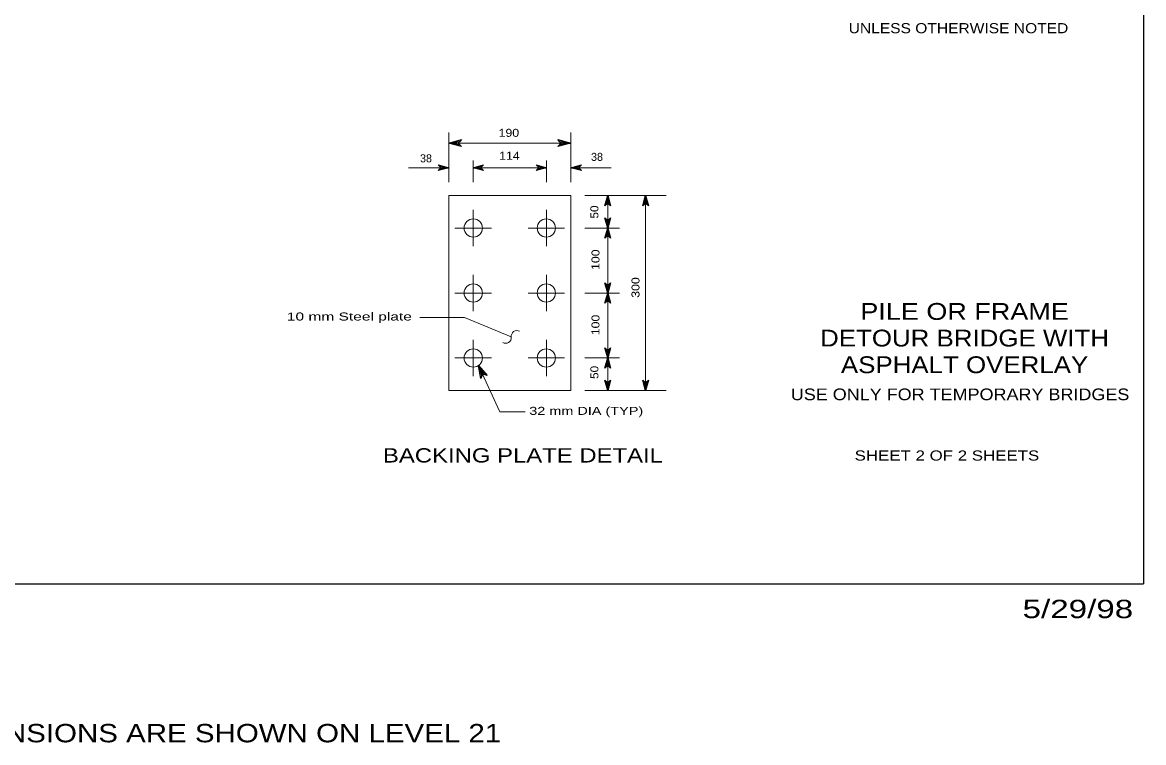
# Model space of a CAD drawing. Extents: x 13426 to 15509, y -9298 to -5111.
# Drawn here: x 15326 to 15509.2, y -5349.3 to -5231.6 of the extents above; entities that cross this region are included whole.
import ezdxf
from ezdxf.enums import TextEntityAlignment as Align

# ---------------------------------------------------------------- set-up
doc = ezdxf.new("R2010")
doc.units = 0
doc.header["$LTSCALE"] = 0.52
for name, color, linetype, lineweight in [('1', 7, 'Continuous', 13), ('15', 7, 'Continuous', 13), ('16', 7, 'Continuous', 25), ('20', 7, 'Continuous', 13), ('3', 7, 'Continuous', 25), ('30', 7, 'Continuous', 25)]:
    doc.layers.add(name, color=color, linetype=linetype, lineweight=lineweight)
doc.layers.add('19', color=7, linetype='Continuous')
doc.layers.add('32', color=7, linetype='Continuous')

msp = doc.modelspace()

# ---------------------------------------------------------------- linework, layer by layer
at = {"layer": '1'}
for p, q in [((15395.687, -5259.907), (15415.586, -5259.907)), ((15415.586, -5259.907), (15415.586, -5291.746))]:
    msp.add_line(p, q, dxfattribs=at)
msp.add_lwpolyline([(15395.687, -5259.907), (15395.687, -5291.746), (15415.586, -5291.746)], dxfattribs=at)
at = {"layer": '15'}
for p, q in [((15395.687, -5257.745), (15395.687, -5249.617)), ((15415.586, -5257.745), (15415.586, -5249.617)), ((15395.687, -5251.346), (15415.586, -5251.346)), ((15389.109, -5255.359), (15395.687, -5255.359)), ((15399.667, -5257.745), (15399.667, -5254.166)), ((15399.667, -5255.359), (15411.606, -5255.359)), ((15411.606, -5257.745), (15411.606, -5254.166)), ((15415.586, -5255.359), (15422.164, -5255.359)), ((15417.863, -5259.907), (15431.195, -5259.907)), ((15427.811, -5259.907), (15427.811, -5291.746)), ((15399.667, -5265.214), (15399.667, -5262.229)), ((15411.606, -5265.214), (15411.606, -5262.229)), ((15399.667, -5265.214), (15396.682, -5265.214)), ((15399.667, -5265.214), (15402.651, -5265.214)), ((15399.667, -5265.214), (15399.667, -5268.199)), ((15411.606, -5265.214), (15408.621, -5265.214)), ((15411.606, -5265.214), (15414.591, -5265.214)), ((15411.606, -5265.214), (15411.606, -5268.199)), ((15417.863, -5265.214), (15423.57, -5265.214)), ((15399.667, -5275.826), (15399.667, -5272.842)), ((15411.606, -5275.826), (15411.606, -5272.842)), ((15399.667, -5275.826), (15396.682, -5275.826)), ((15399.667, -5275.826), (15402.651, -5275.826)), ((15399.667, -5275.826), (15399.667, -5278.812)), ((15411.606, -5275.826), (15408.621, -5275.826)), ((15411.606, -5275.826), (15414.591, -5275.826)), ((15411.606, -5275.826), (15411.606, -5278.812)), ((15417.863, -5275.826), (15423.57, -5275.826)), ((15398.214, -5279.815), (15405.862, -5282.963)), ((15399.667, -5286.439), (15399.667, -5283.455)), ((15411.606, -5286.439), (15411.606, -5283.455)), ((15399.667, -5286.439), (15396.682, -5286.439)), ((15399.667, -5286.439), (15402.651, -5286.439)), ((15399.667, -5286.439), (15399.667, -5289.424)), ((15411.606, -5286.439), (15408.621, -5286.439)), ((15411.606, -5286.439), (15414.591, -5286.439)), ((15411.606, -5286.439), (15411.606, -5289.424)), ((15417.863, -5286.439), (15423.57, -5286.439)), ((15417.863, -5291.746), (15431.195, -5291.746))]:
    msp.add_line(p, q, dxfattribs=at)
for points in [[(15421.633, -5259.907), (15421.633, -5265.214), (15421.633, -5275.826), (15421.633, -5286.439), (15421.633, -5291.746)], [(15400.535, -5287.653), (15404.025, -5295.222), (15408.122, -5295.222)]]:
    msp.add_lwpolyline(points, dxfattribs=at)
for centre, start, end in [((15404.9427, -5283.109), 239.84377, 5.31451), ((15406.7915, -5282.8989), 62.1777, 187.64844)]:
    msp.add_arc(centre, 0.9305, start, end, dxfattribs=at)
at = {"layer": '16'}
for points in [[(15397.444, -5251.576), (15397.769, -5251.914), (15395.687, -5251.346), (15397.769, -5250.778), (15397.444, -5251.116), (15395.687, -5251.346), (15397.444, -5251.576), (15397.214, -5251.346), (15397.444, -5251.116)], [(15413.828, -5251.116), (15413.504, -5250.778), (15415.586, -5251.346), (15413.504, -5251.914), (15413.828, -5251.576), (15415.586, -5251.346), (15413.828, -5251.116), (15414.058, -5251.346), (15413.828, -5251.576)], [(15394.222, -5255.167), (15393.952, -5254.886), (15395.687, -5255.359), (15393.952, -5255.832), (15394.222, -5255.551), (15395.687, -5255.359), (15394.222, -5255.167), (15394.414, -5255.359), (15394.222, -5255.551)], [(15401.073, -5255.543), (15401.333, -5255.813), (15399.667, -5255.359), (15401.333, -5254.905), (15401.073, -5255.175), (15399.667, -5255.359), (15401.073, -5255.543), (15400.889, -5255.359), (15401.073, -5255.175)], [(15410.2, -5255.175), (15409.941, -5254.905), (15411.606, -5255.359), (15409.941, -5255.813), (15410.2, -5255.543), (15411.606, -5255.359), (15410.2, -5255.175), (15410.384, -5255.359), (15410.2, -5255.543)], [(15417.051, -5255.551), (15417.321, -5255.832), (15415.586, -5255.359), (15417.321, -5254.886), (15417.051, -5255.167), (15415.586, -5255.359), (15417.051, -5255.551), (15416.859, -5255.359), (15417.051, -5255.167)], [(15421.449, -5261.313), (15421.178, -5261.573), (15421.633, -5259.907), (15422.087, -5261.573), (15421.817, -5261.313), (15421.633, -5259.907), (15421.449, -5261.313), (15421.633, -5261.129), (15421.817, -5261.313)], [(15427.627, -5261.313), (15427.357, -5261.573), (15427.811, -5259.907), (15428.266, -5261.573), (15427.995, -5261.313), (15427.811, -5259.907), (15427.627, -5261.313), (15427.811, -5261.129), (15427.995, -5261.313)], [(15421.817, -5263.808), (15422.087, -5263.548), (15421.633, -5265.214), (15421.178, -5263.548), (15421.449, -5263.808), (15421.633, -5265.214), (15421.817, -5263.808), (15421.633, -5263.992), (15421.449, -5263.808)], [(15421.449, -5266.62), (15421.178, -5266.879), (15421.633, -5265.214), (15422.087, -5266.879), (15421.817, -5266.62), (15421.633, -5265.214), (15421.449, -5266.62), (15421.633, -5266.436), (15421.817, -5266.62)], [(15421.817, -5274.42), (15422.087, -5274.161), (15421.633, -5275.826), (15421.178, -5274.161), (15421.449, -5274.42), (15421.633, -5275.826), (15421.817, -5274.42), (15421.633, -5274.605), (15421.449, -5274.42)], [(15421.449, -5277.233), (15421.178, -5277.492), (15421.633, -5275.826), (15422.087, -5277.492), (15421.817, -5277.233), (15421.633, -5275.826), (15421.449, -5277.233), (15421.633, -5277.049), (15421.817, -5277.233)], [(15421.817, -5285.033), (15422.087, -5284.774), (15421.633, -5286.439), (15421.178, -5284.774), (15421.449, -5285.033), (15421.633, -5286.439), (15421.817, -5285.033), (15421.633, -5285.217), (15421.449, -5285.033)], [(15421.449, -5287.845), (15421.178, -5288.105), (15421.633, -5286.439), (15422.087, -5288.105), (15421.817, -5287.845), (15421.633, -5286.439), (15421.449, -5287.845), (15421.633, -5287.662), (15421.817, -5287.845)], [(15401.063, -5289.345), (15400.891, -5289.781), (15400.535, -5287.653), (15401.923, -5289.306), (15401.48, -5289.153), (15400.535, -5287.653), (15401.063, -5289.345), (15401.175, -5289.04), (15401.48, -5289.153)], [(15421.817, -5290.34), (15422.087, -5290.08), (15421.633, -5291.746), (15421.178, -5290.08), (15421.449, -5290.34), (15421.633, -5291.746), (15421.817, -5290.34), (15421.633, -5290.524), (15421.449, -5290.34)], [(15427.995, -5290.34), (15428.266, -5290.08), (15427.811, -5291.746), (15427.357, -5290.08), (15427.627, -5290.34), (15427.811, -5291.746), (15427.995, -5290.34), (15427.811, -5290.524), (15427.627, -5290.34)]]:
    msp.add_lwpolyline(points, dxfattribs=at)
at = {"layer": '20'}
msp.add_line((15390.956, -5279.815), (15398.214, -5279.815), dxfattribs=at)
at = {"layer": '3', "lineweight": 13}
for centre in [(15399.6665, -5265.2136), (15411.6059, -5265.2136), (15399.6665, -5275.8264), (15411.6059, -5275.8264), (15399.6665, -5286.4392), (15411.6059, -5286.4392)]:
    msp.add_circle(centre, 1.4924, dxfattribs=at)
at = {"layer": '30'}
for p in [(15509.151, -5111.081), (15181.119, -5323.3)]:
    msp.add_line(p, (15509.151, -5323.3), dxfattribs=at)

# ---------------------------------------------------------------- texts
at = {"layer": '1', "width": 1.35}
msp.add_text('5/29/98', height=3, dxfattribs=at).set_placement((15498.4185, -5328.93), align=Align.CENTER)
at = {"layer": '1', "width": 1.2}
msp.add_text('ENGLISH DIMENSIONS ARE SHOWN ON LEVEL 21', height=3, dxfattribs=at).set_placement((15288.661, -5349.212))
at = {"layer": '19', "width": 1.15}
for s, height, p in [('UNLESS OTHERWISE NOTED', 1.653, (15478.9175, -5233.398)), ('190', 1.307, (15405.4815, -5250.316)), ('114', 1.307, (15405.5705, -5254.055))]:
    msp.add_text(s, height=height, dxfattribs=at).set_placement(p, align=Align.CENTER)
at = {"layer": '19'}
for p in [(15391.9465, -5254.484), (15419.8765, -5254.242)]:
    msp.add_text('38', height=1.307, dxfattribs=at).set_placement(p, align=Align.CENTER)
for s, width, p in [('50', 1.1, (15420.102, -5262.5955)), ('100', 1.15, (15420.281, -5270.384)), ('300', 1.15, (15426.817, -5274.927)), ('100', 1.15, (15420.282, -5281.047)), ('50', 1.1, (15420.102, -5288.7945))]:
    msp.add_text(s, height=1.307, rotation=90, dxfattribs=dict(at, width=width)).set_placement(p, align=Align.CENTER)
at = {"layer": '19', "width": 1.45}
msp.add_text('10 mm Steel plate', height=1.307, dxfattribs=at).set_placement((15389.641, -5280.319), align=Align.RIGHT)
at = {"layer": '19', "width": 1.35}
msp.add_text('32 mm DIA (TYP)', height=1.307, dxfattribs=at).set_placement((15408.808, -5295.727))
at = {"layer": '20'}
for s, height, width, p in [('USE ONLY FOR TEMPORARY BRIDGES', 1.909, 1.15, (15479.18, -5293.334)), ('BACKING PLATE DETAIL', 2.333, 1.25, (15407.779, -5303.51)), ('SHEET 2 OF 2 SHEETS', 1.648, 1.25, (15477.0355, -5303.191))]:
    msp.add_text(s, height=height, dxfattribs=dict(at, width=width)).set_placement(p, align=Align.CENTER)
at = {"layer": '32'}
for s, width, p in [('PILE OR FRAME', 1.2, (15479.913, -5280.207)), ('DETOUR BRIDGE WITH', 1.15, (15479.9125, -5284.562)), ('ASPHALT OVERLAY', 1.15, (15479.913, -5288.917))]:
    msp.add_text(s, height=2.748, dxfattribs=dict(at, width=width)).set_placement(p, align=Align.CENTER)

doc.saveas('drawing.dxf')
